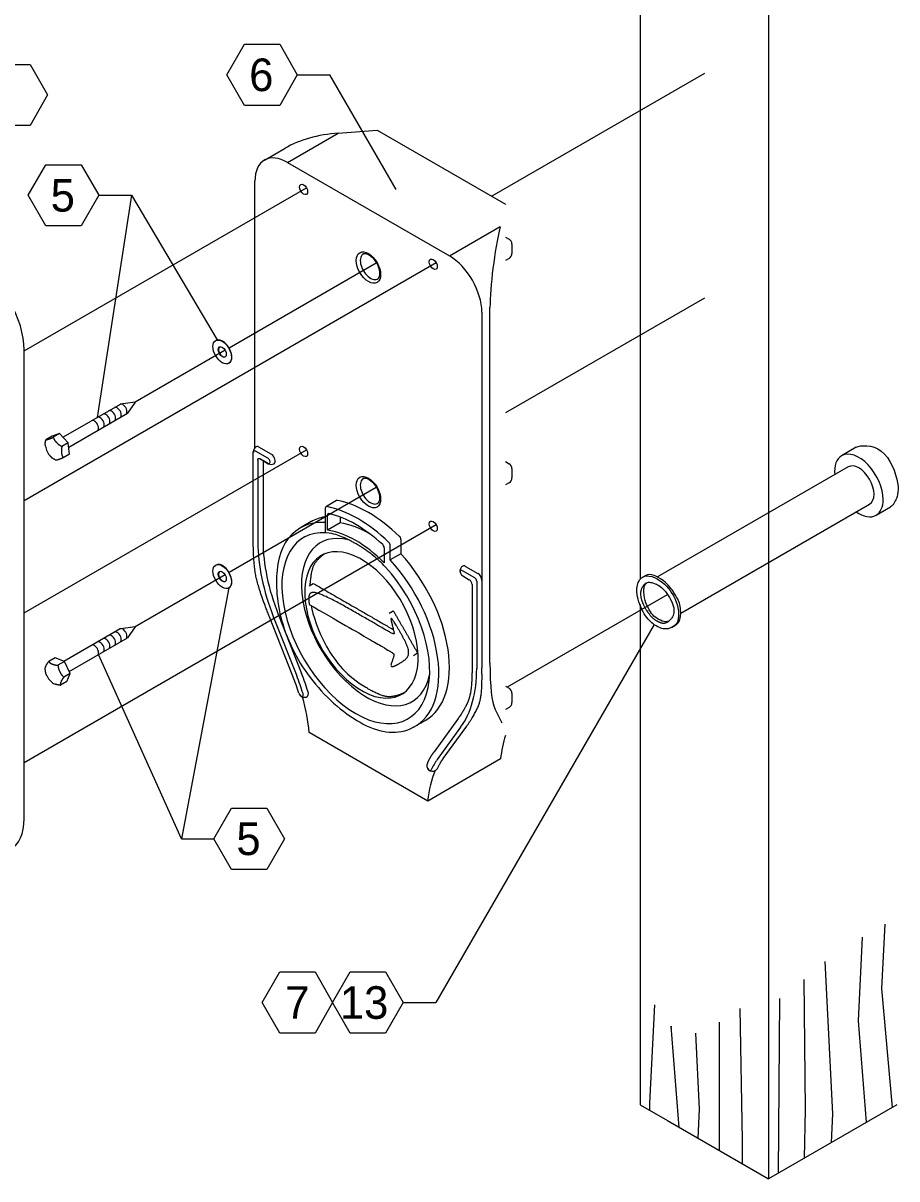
# Model space of a CAD drawing. Extents: x 99862 to 103151, y 100000 to 105076.
# Drawn here: x 102423 to 102852, y 104081 to 104648 of the extents above; entities that cross this region are included whole.
import ezdxf

# ---------------------------------------------------------------- set-up
doc = ezdxf.new("R2010")
doc.units = 0
for name, color, linetype in [('Level 15', 7, 'Continuous'), ('Level 16', 7, 'Continuous'), ('Level 20', 7, 'Continuous'), ('Level 21', 7, 'Continuous'), ('Level 23', 7, 'Continuous'), ('Level 31', 7, 'Continuous'), ('Level 33', 7, 'Continuous'), ('Level 34', 7, 'Continuous'), ('Level 35', 7, 'Continuous'), ('Level 36', 7, 'Continuous'), ('Level 38', 7, 'Continuous'), ('Level 41', 7, 'Continuous')]:
    doc.layers.add(name, color=color, linetype=linetype)

msp = doc.modelspace()

# ---------------------------------------------------------------- linework, layer by layer
at = {"layer": 'Level 15'}
for p, q in [((102557.83, 104622.95), (102573.83, 104622.95)), ((102606.33, 104566.66), (102573.83, 104622.95)), ((102476.4, 104563.82), (102459.67, 104454.78)), ((102460.4, 104563.82), (102476.4, 104563.82)), ((102476.4, 104563.82), (102518.46, 104492.91)), ((102524.22, 104371.13), (102500.92, 104248)), ((102732.9, 104353.12), (102625.8, 104167.63)), ((102500.92, 104248), (102460.22, 104338.37)), ((102500.92, 104248), (102516.92, 104248)), ((102609.8, 104167.63), (102625.8, 104167.63))]:
    msp.add_line(p, q, dxfattribs=at)
at = {"layer": 'Level 16'}
for p, q in [((102757.6, 104623.54), (102653.35, 104563.35)), ((102423.77, 104487.54), (102562.32, 104567.53)), ((102423.77, 104414.05), (102625.95, 104530.78)), ((102596.59, 104530.58), (102524.36, 104488.87)), ((102757.6, 104513.31), (102660.03, 104456.98)), ((102522.4, 104487.74), (102478.19, 104462.22)), ((102423.77, 104358.94), (102562.32, 104438.93)), ((102596.59, 104420.35), (102524.36, 104378.65)), ((102423.77, 104285.46), (102625.95, 104402.19)), ((102522.4, 104377.52), (102478.19, 104351.99)), ((102739.36, 104367.75), (102660.82, 104322.41))]:
    msp.add_line(p, q, dxfattribs=at)
at = {"layer": 'Level 20'}
for points in [[(102523.2, 104622.95), (102531.86, 104637.95), (102549.19, 104637.95), (102557.83, 104622.95), (102549.19, 104607.95), (102531.86, 104607.95), (102523.2, 104622.95)], [(102400.68, 104613.09), (102409.34, 104628.09), (102426.66, 104628.09), (102435.3, 104613.09), (102426.66, 104598.09), (102409.34, 104598.09), (102400.68, 104613.09)], [(102425.77, 104563.82), (102434.43, 104578.81), (102451.75, 104578.81), (102460.4, 104563.82), (102451.75, 104548.82), (102434.43, 104548.82), (102425.77, 104563.82)], [(102516.92, 104248), (102525.58, 104262.99), (102542.9, 104262.99), (102551.55, 104248), (102542.9, 104233), (102525.58, 104233), (102516.92, 104248)], [(102540.55, 104167.63), (102549.21, 104182.63), (102566.53, 104182.63), (102575.18, 104167.63), (102566.53, 104152.63), (102549.21, 104152.63), (102540.55, 104167.63)], [(102575.18, 104167.63), (102583.84, 104182.63), (102601.16, 104182.63), (102609.8, 104167.63), (102601.16, 104152.63), (102583.84, 104152.63), (102575.18, 104167.63)]]:
    msp.add_lwpolyline(points, dxfattribs=at)
at = {"layer": 'Level 21'}
for p, q in [((102832.14, 104440.13), (102824.99, 104436)), ((102828.15, 104430.52), (102734.57, 104376.49)), ((102745.99, 104358.73), (102838.7, 104412.25)), ((102841.87, 104406.77), (102849.02, 104410.9))]:
    msp.add_line(p, q, dxfattribs=at)
for major_axis, start_param, end_param in [((8.44, -14.61), 0.785398, 3.141593), ((8.44, -14.61), 3.141593, 4.037256), ((-5.27, 9.13), 3.141593, 6.283185), ((8.44, -14.61), 0, 0.785398), ((8.44, -14.61), 5.387519, 6.283185)]:
    msp.add_ellipse((102833.43, 104421.39), major_axis=major_axis, ratio=0.57735, start_param=start_param, end_param=end_param, dxfattribs=at)
msp.add_open_spline([(102832.14, 104440.13), (102834.02, 104441.23), (102845.98, 104442.14), (102854.52, 104420.24), (102850.77, 104412.72), (102850.03, 104411.59), (102849.33, 104411.11), (102849.02, 104410.9)], degree=3, dxfattribs=at)
at = {"layer": 'Level 23'}
for p, q in [((102728.49, 104377.02), (102727.4, 104376.39)), ((102741.62, 104351.76), (102742.71, 104352.39))]:
    msp.add_line(p, q, dxfattribs=at)
for points, degree in [([(102741.62, 104351.76), (102741.34, 104351.6), (102740.28, 104351.1), (102738.54, 104350.86), (102736.28, 104351.25), (102733.43, 104352.49), (102727.9, 104357.29), (102723.61, 104368.75), (102725.39, 104375.12), (102727.24, 104376.29), (102727.38, 104376.39), (102727.4, 104376.39)], 3), ([(102727.4, 104376.39), (102729.7, 104377.88), (102737.8, 104374.94), (102744.28, 104364.66), (102744.81, 104359.83), (102744.89, 104359.14), (102744.9, 104358.69), (102744.9, 104358.47)], 3), ([(102746, 104359.1), (102746, 104362.17), (102744.74, 104365.71), (102740.68, 104371.92), (102737.89, 104374.6), (102732.63, 104377.64), (102730.18, 104378), (102728.49, 104377.02)], 3), ([(102734.17, 104354.95), (102733.74, 104355.2), (102733.1, 104355.64), (102731.63, 104356.89), (102730.5, 104358.22), (102726.98, 104363.62), (102726.06, 104369.69), (102727.81, 104372.44), (102728.12, 104372.86), (102728.48, 104373.21), (102728.76, 104373.38), (102728.9, 104373.47)], 3), ([(102727.92, 104369.21), (102727.92, 104371.25), (102728.48, 104372.85), (102729.48, 104373.73)], 2), ([(102728.9, 104373.47), (102729.45, 104373.8), (102730.51, 104374.03), (102732.99, 104373.59), (102738.61, 104370.41), (102743.86, 104360.52), (102741.37, 104355.44), (102739.91, 104354.56), (102739.84, 104354.52)], 3), ([(102740.37, 104354.88), (102738.91, 104354.31), (102737.07, 104354.53), (102733.22, 104356.75), (102731.31, 104358.93), (102728.67, 104363.99), (102727.92, 104366.85), (102727.92, 104369.21)], 3), ([(102744.9, 104358.47), (102744.92, 104355.43), (102743.68, 104352.95), (102741.65, 104351.78)], 2), ([(102742.7, 104352.39), (102742.7, 104352.39), (102742.7, 104352.39), (102742.7, 104352.39), (102744.74, 104353.56), (102746, 104356.03), (102746, 104359.1)], 3), ([(102739.84, 104354.52), (102738.31, 104353.62), (102736.2, 104353.76), (102734.17, 104354.95)], 2)]:
    msp.add_open_spline(points, degree=degree, dxfattribs=at)
at = {"layer": 'Level 31'}
for p, q in [((102789.1, 104740.47), (102789.1, 104081.07)), ((102726.1, 104117.45), (102739.44, 104109.74)), ((102852.1, 104117.45), (102789.1, 104081.07)), ((102739.44, 104109.74), (102789.1, 104081.07))]:
    msp.add_line(p, q, dxfattribs=at)
for points in [[(102726.1, 104776.85), (102726.1, 104375.2)], [(102726.1, 104363.05), (102726.1, 104117.45)], [(102849.91, 104116.18), (102844.73, 104174.51), (102846.35, 104206.12)], [(102837.24, 104108.87), (102833.21, 104158.62), (102835.24, 104199.67)], [(102820.02, 104098.92), (102820.74, 104113.07), (102816.9, 104187.72)], [(102806.7, 104091.24), (102807.23, 104115.19), (102806.53, 104178.93)], [(102730.84, 104114.71), (102730.89, 104118.29), (102733.34, 104166.54)], [(102793.97, 104083.88), (102794.63, 104169.53)], [(102776.31, 104088.41), (102776.39, 104099.98), (102775.23, 104164.66)], [(102745.32, 104106.31), (102741.29, 104156.06), (102741.26, 104155.37)], [(102765, 104094.98), (102765, 104158.04)], [(102754.56, 104101.08), (102755.28, 104115.23), (102753.37, 104152.52)]]:
    msp.add_lwpolyline(points, dxfattribs=at)
at = {"layer": 'Level 33'}
for p, q in [((102552.95, 104579.97), (102577.86, 104594.35)), ((102577.86, 104594.35), (102597.03, 104595.86)), ((102597.03, 104595.86), (102660.03, 104559.49)), ((102541.7, 104581.09), (102551.81, 104586.92)), ((102552.95, 104579.97), (102632.5, 104534.04)), ((102537.04, 104439.96), (102537.04, 104570.79)), ((102632.5, 104534.04), (102657.41, 104548.43)), ((102660.03, 104543.32), (102661.75, 104542.32)), ((102663.16, 104539.89), (102663.16, 104535.3)), ((102661.75, 104532.86), (102660.03, 104531.86)), ((102648.41, 104506.49), (102648.41, 104374.82)), ((102652.39, 104334.26), (102652.39, 104508.78)), ((102536.22, 104395.11), (102536.22, 104437.97)), ((102543.35, 104434.85), (102537.38, 104438.3)), ((102545, 104436.82), (102539.03, 104440.27)), ((102538.49, 104433.82), (102538.49, 104393.52)), ((102543.35, 104432.29), (102539.59, 104434.46)), ((102540.44, 104433.91), (102543.59, 104432.09)), ((102541.02, 104432.23), (102541.02, 104393.96)), ((102660.03, 104433.09), (102661.75, 104432.1)), ((102663.16, 104429.66), (102663.16, 104425.07)), ((102590.28, 104424.83), (102590.21, 104424.78)), ((102661.75, 104422.63), (102660.03, 104421.64)), ((102571.47, 104409.71), (102571.47, 104398.44)), ((102577.11, 104413.98), (102572.19, 104411.14)), ((102597.24, 104412.61), (102597.24, 104412.61)), ((102564.6, 104403.64), (102559.41, 104400.64)), ((102572.6, 104399.47), (102572.6, 104406.93)), ((102578.81, 104405.94), (102578.81, 104403.05)), ((102578.81, 104403.05), (102572.6, 104399.47)), ((102608.64, 104394.96), (102608.64, 104387.83)), ((102600.45, 104390.85), (102600.45, 104383.4)), ((102603.44, 104384.83), (102603.43, 104391.95)), ((102608.64, 104387.83), (102603.44, 104384.83)), ((102640.46, 104381.71), (102646.42, 104378.27)), ((102638.81, 104379.74), (102644.77, 104376.29)), ((102639.05, 104376.98), (102642.21, 104375.16)), ((102643.61, 104372.72), (102643.61, 104333.11)), ((102645.88, 104374.38), (102645.88, 104331.52)), ((102648.41, 104374.82), (102648.41, 104331.96)), ((102555.63, 104327.83), (102544.15, 104356.93)), ((102546.06, 104357.12), (102557.54, 104328.03)), ((102548.47, 104358.16), (102559.95, 104329.06)), ((102660.03, 104322.87), (102661.75, 104321.87)), ((102663.16, 104319.43), (102663.16, 104314.84)), ((102658.45, 104304.79), (102654.83, 104311.91)), ((102661.75, 104312.41), (102660.03, 104311.41)), ((102615.66, 104303.21), (102620.85, 104306.21)), ((102636.42, 104306.55), (102624.94, 104290.71)), ((102638, 104302.74), (102626.52, 104286.9)), ((102629.5, 104287.41), (102640.98, 104303.25)), ((102621.82, 104266.5), (102563.64, 104300.08)), ((102657.61, 104287.16), (102621.82, 104266.5))]:
    msp.add_line(p, q, dxfattribs=at)
for centre, radius, start, end in [((102660.35, 104539.89), 2.81, 0, 60), ((102660.35, 104535.3), 2.81, 300, 0), ((102539.03, 104437.97), 2.81, 120, 180), ((102545, 104434.53), 2.81, 240, 300), ((102660.35, 104429.66), 2.81, 0, 60), ((102660.35, 104425.07), 2.81, 300, 0), ((102640.46, 104379.41), 2.81, 120, 240), ((102640.8, 104372.72), 2.81, 360, 60), ((102561.27, 104320.23), 2.79, 197.7565, 251.962), ((102660.35, 104319.43), 2.81, 0, 60), ((102561.27, 104320.23), 2.79, 251.962, 300.4656), ((102660.35, 104314.84), 2.81, 300, 0), ((102624.18, 104283.95), 2.81, 154.0815, 299.6218), ((102624.18, 104283.95), 2.81, 299.6218, 328.2181)]:
    msp.add_arc(centre, radius, start, end, dxfattribs=at)
for centre, major_axis, ratio, start_param, end_param in [((102577.86, 104575.98), (36.79, 3.84), 0.494566, 1.519169, 2.304567), ((102552.95, 104561.6), (-11.25, 19.49), 0.57735, 6.267379, 7.068583), ((102552.95, 104561.6), (-11.25, 19.49), 0.57735, 5.497787, 6.26552), ((102657.41, 104530.05), (3.85, 28.1), 0.114691, 0.874148, 2.444944), ((102593.72, 104528.92), (-3.52, 6.09), 0.57735, 6.244605, 9.508637), ((102632.5, 104515.67), (11.25, -19.49), 0.57735, 0.785398, 2.356194), ((102537.38, 104437.02), (0.78, -1.36), 0.57735, 2.356194, 3.926991), ((102539.03, 104437.97), (-1.41, 2.44), 0.57735, 5.497787, 6.283185), ((102539.03, 104437.97), (4.13, -4.48), 0.368973, 5.220152, 5.415219), ((102543.01, 104431.08), (-1.41, 2.44), 0.57735, 0.159548, 0.785398), ((102543.35, 104433.57), (0.78, -1.36), 0.57735, 5.497787, 8.63938), ((102545, 104434.53), (-1.41, 2.44), 0.57735, 3.141593, 5.497787), ((102593.72, 104418.7), (-3.52, 6.09), 0.57735, 6.244605, 9.508637), ((102572.51, 104409.87), (0.26, 1.38), 0.731418, 0.561152, 1.823018), ((102587.52, 104350), (33.75, -58.46), 0.57735, 2.031363, 2.681026), ((102577.81, 104412.76), (-0.7, 1.22), 0.57735, 5.822618, 6.283185), ((102592.73, 104353), (-33.75, 58.46), 0.57735, 5.172956, 5.822618), ((102592.73, 104354.92), (-28.13, 48.71), 0.57735, 6.069803, 6.28319), ((102573.6, 104406.35), (0.7, -1.22), 0.57735, 2.649261, 3.926991), ((102586.52, 104349.42), (32.34, -56.02), 0.57735, 2.063128, 2.649261), ((102586.54, 104351.35), (25.65, -44.43), 0.57735, 2.770312, 8.225262), ((102587.53, 104351.92), (28.13, -48.71), 0.57735, 2.771884, 3.141593), ((102571.62, 104398.35), (0.107, -0.186), 0.57735, 3.926991, 5.90159), ((102586.52, 104349.42), (27.55, -47.71), 0.57735, 1.990752, 2.721637), ((102592.73, 104353), (-27.55, 47.71), 0.57735, 5.467511, 5.86323), ((102593.07, 104362.01), (-38.59, 66.84), 0.57735, 0.785398, 1.318407), ((102594.72, 104362.96), (37.97, -65.76), 0.57735, 3.926991, 4.46), ((102599.45, 104391.43), (0.7, -1.22), 0.57735, 0.785398, 2.063128), ((102602.43, 104392.53), (-0.7, 1.22), 0.57735, 3.926991, 5.172956), ((102607.64, 104395.54), (-0.7, 1.22), 0.57735, 3.926991, 5.172956), ((102592.73, 104354.92), (-28.13, 48.71), 0.57735, 3.141593, 5.08627), ((102587.53, 104351.92), (28.13, -48.71), 0.57735, 6.254516, 8.227863), ((102640.46, 104379.41), (-1.41, 2.44), 0.57735, 5.497787, 6.283185), ((102638.81, 104378.46), (0.78, -1.36), 0.57735, 2.356194, 5.497787), ((102644.77, 104375.01), (0.78, -1.36), 0.57735, 0.785398, 2.356194), ((102646.42, 104375.97), (-1.41, 2.44), 0.57735, 3.926991, 5.497787), ((102589.09, 104364.3), (40.16, -69.56), 0.57735, 0.252389, 0.785398), ((102669.97, 104408.71), (-13.48, -98.36), 0.114691, 5.586537, 6.119546), ((102558.24, 104328.89), (2.62, 1.03), 0.203894, 3.101194, 3.181991), ((102508.62, 104322.95), (-38.59, 66.84), 0.57735, 4.339992, 4.46), ((102508.62, 104322.95), (40.16, -69.56), 0.57735, 1.198399, 1.318408), ((102510.28, 104323.9), (-40.78, 70.64), 0.57735, 4.339992, 4.46), ((102559.63, 104319.31), (0.78, -1.36), 0.57735, 4.712389, 7.481585), ((102561.28, 104320.26), (-1.41, 2.44), 0.57735, 3.141594, 4.339992), ((102508.29, 104325.05), (-39.38, 68.2), 0.57735, 4.035936, 4.286649), ((102712.97, 104248.21), (-39.38, 68.2), 0.57735, 0.470176, 0.676453), ((102673.53, 104227.74), (-38.59, 66.84), 0.57735, 0.252389, 0.372397), ((102622.53, 104282.99), (0.78, -1.36), 0.57735, 4.712389, 6.655582), ((102677.17, 104227.55), (-39.38, 68.2), 0.57735, 0.400156, 0.676453)]:
    msp.add_ellipse(centre, major_axis=major_axis, ratio=ratio, start_param=start_param, end_param=end_param, dxfattribs=at)
for centre, major_axis in [((102560.91, 104566.72), (-1.41, 2.44)), ((102592.73, 104528.35), (-4.22, 7.31)), ((102624.55, 104529.97), (-1.41, 2.44)), ((102560.91, 104438.12), (-1.41, 2.44)), ((102592.73, 104418.12), (-4.22, 7.31)), ((102624.55, 104401.37), (-1.41, 2.44))]:
    msp.add_ellipse(centre, major_axis=major_axis, ratio=0.57735, dxfattribs=at)
for points, degree in [([(102590.35, 104535.09), (102590.88, 104535.33), (102591.83, 104535.28), (102593.02, 104534.59)], 2), ([(102593.02, 104534.59), (102595.58, 104533.16), (102599.12, 104526.63), (102597.97, 104523.45), (102597.52, 104523.02)], 3), ([(102538.49, 104433.82), (102538.49, 104433.96), (102538.5, 104434.1), (102538.52, 104434.22), (102538.54, 104434.35), (102538.58, 104434.47), (102538.64, 104434.55), (102538.69, 104434.61), (102538.74, 104434.65), (102538.8, 104434.67), (102538.87, 104434.69), (102538.94, 104434.7), (102539.01, 104434.69), (102539.14, 104434.68), (102539.28, 104434.62), (102539.41, 104434.56), (102539.47, 104434.53), (102539.53, 104434.5), (102539.59, 104434.46)], 3), ([(102590.35, 104424.86), (102590.88, 104425.1), (102591.83, 104425.05), (102593.02, 104424.37)], 2), ([(102593.02, 104424.37), (102595.58, 104422.93), (102599.12, 104416.4), (102597.97, 104413.23), (102597.52, 104412.8)], 3), ([(102559.41, 104400.64), (102552.92, 104396.6), (102546.49, 104385.11), (102547.9, 104354.9), (102563.49, 104324.24), (102590.62, 104301), (102607.14, 104298.67), (102615.03, 104302.86)], 3), ([(102601.14, 104381.27), (102598.83, 104383.72), (102596.43, 104385.93), (102592.77, 104388.79), (102591.55, 104389.66), (102589.13, 104391.26), (102587.93, 104392), (102585.43, 104393.44), (102584.13, 104394.14), (102581.59, 104395.41), (102580.34, 104395.97), (102576.66, 104397.35), (102574.26, 104397.91), (102571.94, 104398.13)], 3), ([(102544.14, 104356.95), (102538.98, 104370), (102536.21, 104383.29), (102536.22, 104395.11)], 2), ([(102643.61, 104333.11), (102643.63, 104322.14), (102641.03, 104312.86), (102636.42, 104306.55)], 2), ([(102640.98, 104303.25), (102646.42, 104311.1), (102648.76, 104320.73), (102648.41, 104331.96)], 2), ([(102624.94, 104290.71), (102623.71, 104289.01), (102622.61, 104287.16), (102621.65, 104285.18)], 2), ([(102626.57, 104282.47), (102628.07, 104285.3), (102628.76, 104286.39), (102629.5, 104287.41)], 2)]:
    msp.add_open_spline(points, degree=degree, dxfattribs=at)
at = {"layer": 'Level 34'}
for centre, major_axis, start_param, end_param in [((102591.71, 104354.34), (22.5, -38.97), 2.632698, 6.851151), ((102589.32, 104352.96), (19.69, -34.1), 2.394599, 8.675608)]:
    msp.add_ellipse(centre, major_axis=major_axis, ratio=0.57735, start_param=start_param, end_param=end_param, dxfattribs=at)
at = {"layer": 'Level 35'}
for p, q in [((102563.64, 104372.22), (102565.63, 104373.37)), ((102602.97, 104358.7), (102604.96, 104359.85)), ((102614.9, 104338.03), (102616.89, 104339.18))]:
    msp.add_line(p, q, dxfattribs=at)
for points, degree in [([(102565.63, 104373.37), (102585.29, 104362.02), (102604.96, 104350.67)], 2), ([(102563.64, 104363.04), (102563.02, 104367.99), (102563.64, 104372.22), (102583.94, 104360.5), (102604.24, 104348.78), (102605.62, 104347.99), (102605.18, 104349.75), (102604.07, 104354.23), (102602.97, 104358.7), (102608.93, 104348.37), (102614.9, 104338.03), (102608.93, 104334.59), (102602.97, 104331.15), (102604.07, 104334.34), (102605.18, 104337.54), (102605.62, 104338.8), (102604.24, 104339.6), (102583.94, 104351.32), (102563.64, 104363.04)], 4), ([(102604.96, 104359.85), (102610.92, 104349.52), (102616.89, 104339.18)], 2)]:
    msp.add_open_spline(points, degree=degree, dxfattribs=at)
at = {"layer": 'Level 36'}
for points, degree in [([(102571.07, 104387.77), (102566.92, 104384.65), (102564.49, 104379.13), (102564, 104372.43)], 2), ([(102564.59, 104362.49), (102565.36, 104358.17), (102570.38, 104342.02), (102582.44, 104327.55), (102591.43, 104322.36)], 3), ([(102591.43, 104322.36), (102598.12, 104318.46), (102604.98, 104317.43), (102610.33, 104319.73)], 2)]:
    msp.add_open_spline(points, degree=degree, dxfattribs=at)
at = {"layer": 'Level 38'}
for p, q in [((102470.84, 104461.22), (102442.88, 104445.08)), ((102478.19, 104462.22), (102471.12, 104461.33)), ((102478.19, 104462.22), (102474.54, 104456.86)), ((102445.69, 104440.21), (102474.54, 104456.86)), ((102437.57, 104445.67), (102434.42, 104443.85)), ((102441.19, 104446.85), (102437.57, 104445.67)), ((102441.19, 104446.85), (102438.03, 104445.03)), ((102445.44, 104442.4), (102441.19, 104446.85)), ((102445.44, 104442.4), (102442.29, 104440.58)), ((102446.08, 104436.78), (102445.44, 104442.4)), ((102446.08, 104436.78), (102442.93, 104434.96)), ((102470.84, 104350.99), (102443.25, 104335.07)), ((102478.19, 104351.99), (102471.17, 104351.11)), ((102478.19, 104351.99), (102474.54, 104346.64)), ((102445.9, 104330.1), (102474.54, 104346.64)), ((102438.97, 104336.8), (102435.81, 104334.98)), ((102443.51, 104334.96), (102438.97, 104336.8)), ((102443.51, 104334.96), (102440.36, 104333.14)), ((102446.37, 104329.16), (102443.51, 104334.96)), ((102444.68, 104325.2), (102441.53, 104323.38)), ((102446.37, 104329.16), (102443.22, 104327.34)), ((102444.68, 104325.2), (102446.37, 104329.16))]:
    msp.add_line(p, q, dxfattribs=at)
for centre, major_axis in [((102520.99, 104486.93), (-3.22, 5.58)), ((102520.99, 104486.93), (1.41, -2.44)), ((102520.99, 104376.71), (-3.22, 5.58)), ((102520.99, 104376.71), (1.41, -2.44))]:
    msp.add_ellipse(centre, major_axis=major_axis, ratio=0.57735, dxfattribs=at)
for centre, major_axis, start_param, end_param in [((102521.13, 104487.01), (-3.22, 5.58), 3.119941, 6.283185), ((102521.13, 104487.01), (1.41, -2.44), 3.19121, 6.233568), ((102438.16, 104439.11), (2.81, -4.87), 4.066603, 5.113801), ((102521.13, 104376.79), (-3.22, 5.58), 4.16506, 6.304836), ((102521.13, 104376.79), (1.41, -2.44), 3.19121, 6.233568), ((102521.13, 104376.79), (-3.22, 5.58), 3.119941, 4.16506), ((102438.16, 104328.88), (2.81, -4.87), 4.59906, 5.646257)]:
    msp.add_ellipse(centre, major_axis=major_axis, ratio=0.57735, start_param=start_param, end_param=end_param, dxfattribs=at)
for points in [[(102434.22, 104440.74), (102434.11, 104441.71), (102434.21, 104442.77), (102434.42, 104443.85)], [(102434.42, 104443.85), (102434.69, 104443.86), (102435.09, 104443.94), (102435.71, 104444.14)], [(102435.71, 104444.14), (102436.33, 104444.34), (102437.15, 104444.66), (102438.03, 104445.03)], [(102438.03, 104445.03), (102438.41, 104444.14), (102438.92, 104443.27), (102439.65, 104442.51)], [(102439.65, 104442.51), (102440.38, 104441.74), (102441.31, 104441.11), (102442.29, 104440.58)], [(102442.29, 104440.58), (102442.09, 104439.51), (102441.99, 104438.44), (102442.1, 104437.47)], [(102439.31, 104433.78), (102438.33, 104434.32), (102437.4, 104434.95), (102436.67, 104435.71)], [(102440.61, 104434.08), (102439.99, 104433.87), (102439.59, 104433.8), (102439.31, 104433.78)], [(102442.93, 104434.96), (102442.05, 104434.6), (102441.23, 104434.28), (102440.61, 104434.08)], [(102442.1, 104437.47), (102442.21, 104436.51), (102442.52, 104435.68), (102442.93, 104434.96)], [(102434.13, 104331.02), (102434.09, 104331.47), (102434.17, 104332.02), (102434.46, 104332.7)], [(102435.05, 104327.82), (102434.56, 104328.82), (102434.28, 104329.91), (102434.13, 104331.02)], [(102434.46, 104332.7), (102434.75, 104333.38), (102435.24, 104334.17), (102435.81, 104334.98)], [(102435.81, 104334.98), (102436.23, 104334.51), (102436.79, 104334.08), (102437.57, 104333.76)], [(102437.57, 104333.76), (102438.35, 104333.45), (102439.32, 104333.26), (102440.36, 104333.14)], [(102440.36, 104333.14), (102440.51, 104332.04), (102440.78, 104330.94), (102441.27, 104329.94)], [(102441.27, 104329.94), (102441.77, 104328.95), (102442.45, 104328.09), (102443.22, 104327.34)], [(102441.86, 104325.06), (102441.57, 104324.38), (102441.5, 104323.83), (102441.53, 104323.38)], [(102443.22, 104327.34), (102442.64, 104326.53), (102442.15, 104325.74), (102441.86, 104325.06)], [(102441.53, 104323.38), (102440.5, 104323.49), (102439.53, 104323.68), (102438.75, 104324)]]:
    msp.add_open_spline(points, degree=2, dxfattribs=at)
at = {"layer": 'Level 41'}
msp.add_line((102423.77, 104257.9), (102423.77, 104487.91), dxfattribs=at)
for centre, major_axis, start_param, end_param in [((102399.91, 104501.68), (-16.88, 29.23), 3.926991, 5.497787), ((102472.24, 104458.79), (1.41, -2.44), 6.28318, 9.424778), ((102461.08, 104452.34), (1.41, -2.44), 6.28318, 9.424778), ((102463.87, 104453.95), (1.41, -2.44), 6.28318, 9.424778), ((102466.66, 104455.56), (1.41, -2.44), 6.28318, 9.424778), ((102469.45, 104457.17), (1.41, -2.44), 6.28318, 9.424778), ((102458.29, 104450.73), (1.41, -2.44), 6.28318, 9.424778), ((102466.66, 104345.34), (1.41, -2.44), 6.28318, 9.424778), ((102469.45, 104346.95), (1.41, -2.44), 6.28318, 9.424778), ((102472.24, 104348.56), (1.41, -2.44), 6.28318, 9.424778), ((102458.29, 104340.5), (1.41, -2.44), 6.28318, 9.424778), ((102461.08, 104342.11), (1.41, -2.44), 6.28318, 9.424778), ((102463.87, 104343.73), (1.41, -2.44), 6.28318, 9.424778), ((102399.91, 104271.68), (16.88, -29.23), 0, 0.785398)]:
    msp.add_ellipse(centre, major_axis=major_axis, ratio=0.57735, start_param=start_param, end_param=end_param, dxfattribs=at)

# ---------------------------------------------------------------- texts
at = {"layer": 'Level 20'}
for s, p in [('6', (102534.21, 104614.95)), ('5', (102436.78, 104555.82)), ('5', (102527.93, 104240)), ('7', (102551.92, 104159.63)), ('13', (102578.72, 104159.63))]:
    msp.add_text(s, height=16, dxfattribs=at).set_placement(p)

doc.saveas('drawing.dxf')
